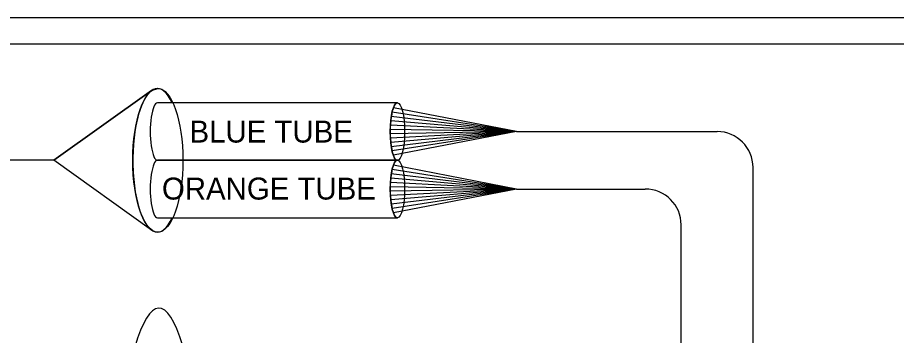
# Model space of a CAD drawing. Extents: x 1805893 to 1833564, y 708898 to 716199.
# Drawn here: x 1831608.1 to 1831730.4, y 714465.3 to 714509.6 of the extents above; entities that cross this region are included whole.
import ezdxf

# ---------------------------------------------------------------- set-up
doc = ezdxf.new("R2010")
doc.units = 0
doc.layers.add('BR_P_Sub_Hidden', color=7, linetype='Continuous')
doc.layers.add('SH_Data', color=7, linetype='Continuous')

msp = doc.modelspace()

# ---------------------------------------------------------------- linework, layer by layer
at = {"layer": 'BR_P_Sub_Hidden'}
for points in [[(1831500.32, 714509.57), (1831957.51, 714509.57), (1831957.51, 714273.91), (1831500.32, 714273.91)], [(1831570.12, 714505.91), (1831894.14, 714505.91), (1831894.14, 714279.3), (1831570.12, 714279.3)]]:
    msp.add_lwpolyline(points, close=True, dxfattribs=at)
at = {"layer": 'SH_Data'}
for p, q in [((1831626.73, 714499.41), (1831627.6, 714499.69)), ((1831626.73, 714499.41), (1831613.14, 714489.68)), ((1831613.14, 714489.68), (1831626.73, 714499.41)), ((1831660.94, 714497.68), (1831627.54, 714497.68)), ((1831677.5, 714493.68), (1831660.21, 714496.38)), ((1831677.5, 714493.68), (1831660.38, 714496.98)), ((1831677.5, 714493.68), (1831660.02, 714495.18)), ((1831677.5, 714493.68), (1831660.09, 714495.78)), ((1831677.5, 714493.68), (1831659.95, 714493.98)), ((1831677.5, 714493.68), (1831659.95, 714493.38)), ((1831677.5, 714493.68), (1831659.97, 714494.58)), ((1831677.5, 714493.68), (1831659.97, 714492.78)), ((1831677.5, 714493.68), (1831660.02, 714492.18)), ((1831677.5, 714493.68), (1831660.09, 714491.58)), ((1831677.5, 714493.68), (1831660.21, 714490.98)), ((1831677.5, 714493.68), (1831660.38, 714490.38)), ((1831677.5, 714493.68), (1831705.44, 714493.68)), ((1831613.14, 714489.68), (1831547.53, 714489.68)), ((1831626.73, 714479.96), (1831613.14, 714489.68)), ((1831626.73, 714479.96), (1831613.14, 714489.68)), ((1831627.54, 714489.68), (1831660.94, 714489.68)), ((1831660.94, 714489.68), (1831627.54, 714489.68)), ((1831677.5, 714485.68), (1831660.38, 714488.98)), ((1831710.44, 714454.4), (1831710.44, 714488.68)), ((1831677.5, 714485.68), (1831660.09, 714487.78)), ((1831677.5, 714485.68), (1831660.21, 714488.38)), ((1831677.5, 714485.68), (1831659.97, 714486.58)), ((1831677.5, 714485.68), (1831660.02, 714487.18)), ((1831677.5, 714485.68), (1831659.95, 714485.98)), ((1831677.5, 714485.68), (1831659.95, 714485.38)), ((1831677.5, 714485.68), (1831659.97, 714484.78)), ((1831677.5, 714485.68), (1831660.02, 714484.18)), ((1831677.5, 714485.68), (1831660.09, 714483.58)), ((1831677.5, 714485.68), (1831660.21, 714482.98)), ((1831677.5, 714485.68), (1831660.38, 714482.38)), ((1831677.5, 714485.68), (1831695.44, 714485.68)), ((1831627.54, 714481.68), (1831660.94, 714481.68)), ((1831700.44, 714454.4), (1831700.44, 714480.68))]:
    msp.add_line(p, q, dxfattribs=at)
for centre in [(1831705.44, 714488.68), (1831695.44, 714480.68)]:
    msp.add_arc(centre, 5, 0, 90, dxfattribs=at)
for centre, major_axis, ratio, start_param, end_param in [((1831627.54, 714489.68), (0, 10.01), 0.341831, 5.638089, 10.069875), ((1831627.54, 714489.68), (0, 10.01), 0.341831, 6.265717, 9.184951), ((1831627.54, 714493.68), (0, 4), 0.25, 0, 3.141593), ((1831660.94, 714493.68), (0, 4), 0.25, 0, 3.141593), ((1831627.54, 714485.68), (0, 4), 0.25, 0, 3.141593), ((1831660.94, 714485.68), (0, 4), 0.25, 0, 3.141593), ((1831627.75, 714382.99), (0, -86.09), 0.112175, 2.561295, 6.863483), ((1831627.75, 714382.99), (0, -86.09), 0.112175, 2.561295, 6.863483)]:
    msp.add_ellipse(centre, major_axis=major_axis, ratio=ratio, start_param=start_param, end_param=end_param, dxfattribs=at)
for centre, major_axis, ratio in [((1831627.6, 714489.68), (0, -10.02), 0.347607), ((1831660.94, 714493.68), (0, 4), 0.25), ((1831660.94, 714485.68), (0, 4), 0.25)]:
    msp.add_ellipse(centre, major_axis=major_axis, ratio=ratio, dxfattribs=at)

# ---------------------------------------------------------------- texts
for s, height, p in [('BLUE TUBE', 3.06, (1831632.01, 714492.15)), ('ORANGE TUBE', 3.0596, (1831628.17, 714484.21))]:
    msp.add_text(s, height=height, dxfattribs=at).set_placement(p)

doc.saveas('drawing.dxf')
